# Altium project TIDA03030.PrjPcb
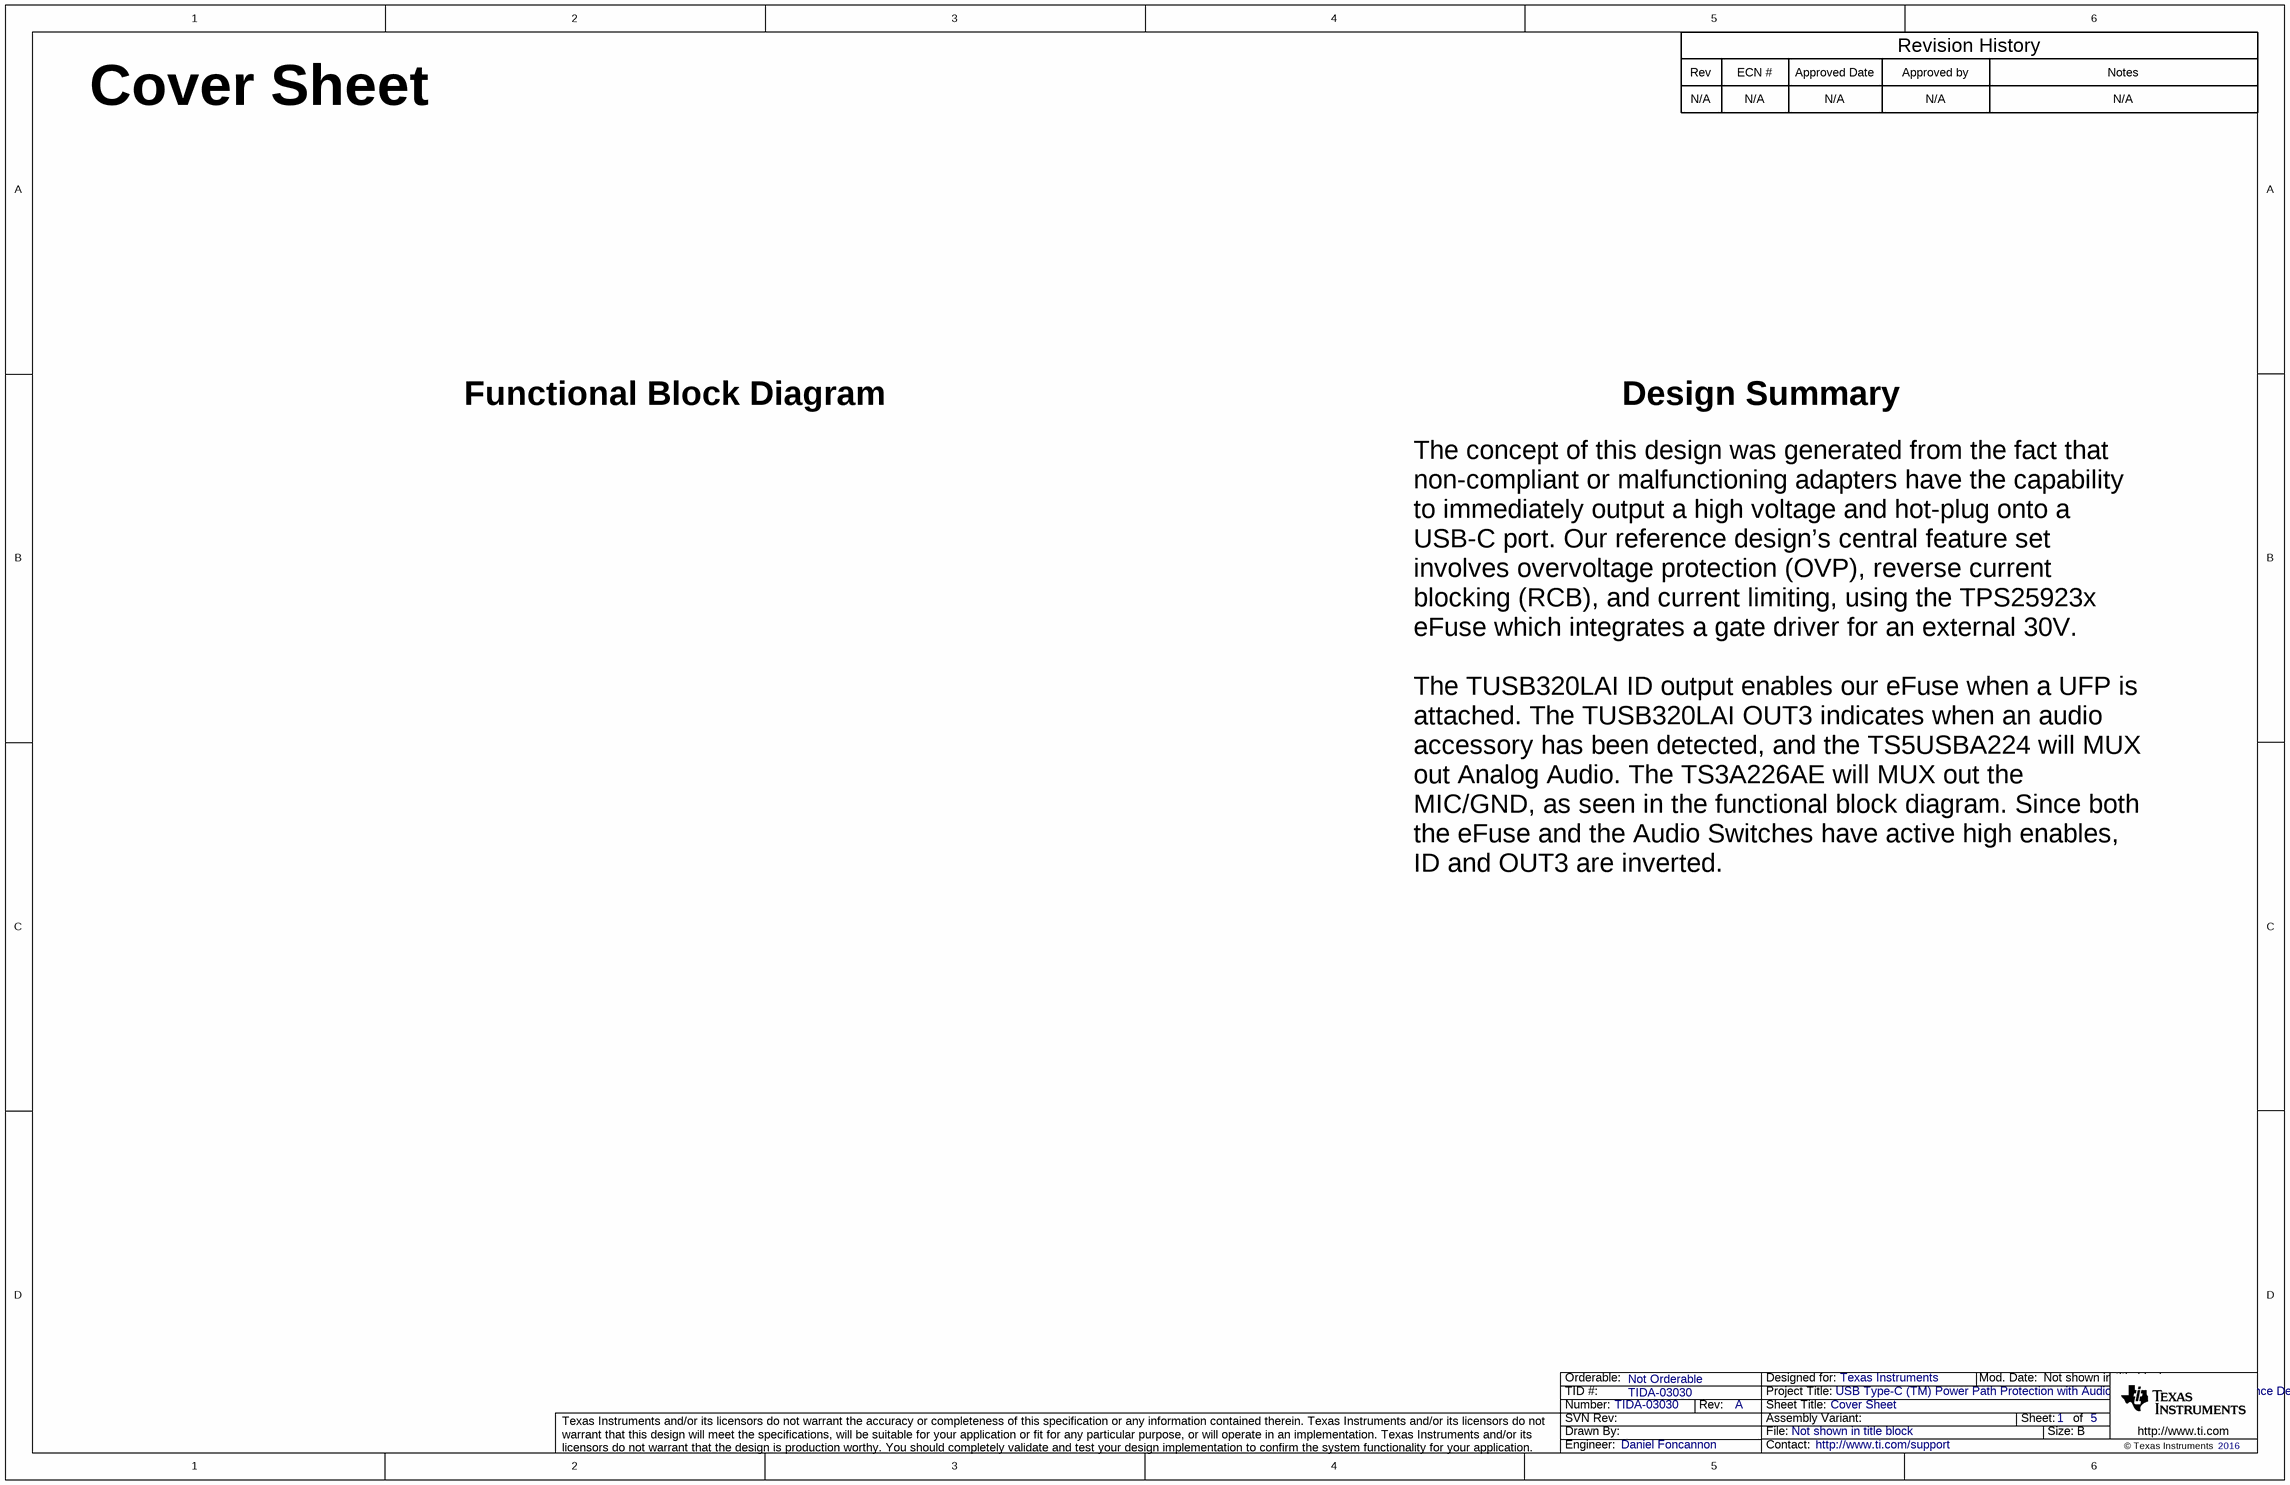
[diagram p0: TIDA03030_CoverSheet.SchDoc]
TID: TIDA-03030; TechSupport: http://www.ti.com/support; SCH_Rev: A; PRJ_Title: USB Type-C (TM) Power Path Protection with Audio Accessory Support Reference Design; PRJ_Number: TIDA-03030; PRJ_Engineer: Daniel Foncannon; PRJ_Customer: Texas Instruments; PCB_Rev: A; PCB_Layout: TIDA; EVM_Orderable: Not Orderable; CopyrightYear: 2016
5 sheets, 102 parts. Net scope: global (net labels, ports and power ports of the same name join across sheets).
Board file: TIDA03030_PCB.PcbDoc
Sheets:
  TIDA03030_CoverSheet.SchDoc
  TIDA03030_Hardware.SchDoc
  TIDA03030_Power.SchDoc
  TIDA03030_Controller&Switches.SchDoc
  TIDA03030_Connectors.SchDoc

## Sheet TIDA03030_CoverSheet.SchDoc: Cover Sheet
size 431 x 279 mm; Date: Not shown in title block; ApprovedBy: Not shown in title block; CheckedBy: Not shown in title block; Author: Not shown in title block; CompanyName: Not shown in title block; Engineer: Not shown in title block; Organization: Not shown in title block; Address1: Not shown in title block; Address2: Not shown in title block; Address3: Not shown in title block; Address4: Not shown in title block; DocumentNumber: 1; Revision: Use project parameter SCH_Rev; SheetNumber: 1; SheetTotal: 5; PageSetup: Record=PageOptions¦CenterHorizontal=True¦CenterVertical=True¦PrintScale=1.00¦XCorrection=1.00¦YCorrection=1.00¦PrintKind=0¦BorderSize=5000000¦LeftOffset=0¦BottomOffset=0¦Orientation=2¦PaperLength=1000¦PaperWidth=1000¦Scale=100¦PaperSource=15¦PrintQuality=600¦MediaType=1¦DitherType=10¦PaperKind=Letter¦PrintScaleMode=1

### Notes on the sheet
- Cover Sheet
- Rev
- N/A
- ECN #
- Approved Date
- Approved by
- Revision History
- Notes
- Functional Block Diagram
- Design Summary
- The concept of this design was generated from the fact that non-compliant or malfunctioning adapters have the capability to immediately output a high voltage and hot-plug onto a USB-C port. Our reference design’s central feature set involves overvoltage protection (OVP), reverse current blocking (RCB), and current limiting, using the TPS25923x eFuse which integrates a gate driver for an external 30V.
  The TUSB320LAI ID output enables our eFuse when a UFP is attached. The TUSB320LAI OUT3 indicates when an audio accessory has been detected, and the TS5USBA224 will MUX out Analog Audio. The TS3A226AE will MUX out the MIC/GND, as seen in the functional block diagram. Since both the eFuse and the Audio Switches have active high enables, ID and OUT3 are inverted.

## Sheet TIDA03030_Hardware.SchDoc: Board Hardware
size 431 x 279 mm; Date: Not shown in title block; ApprovedBy: Not shown in title block; CheckedBy: Not shown in title block; Author: Not shown in title block; CompanyName: Not shown in title block; Engineer: Not shown in title block; Organization: Not shown in title block; Address1: Not shown in title block; Address2: Not shown in title block; Address3: Not shown in title block; Address4: Not shown in title block; DocumentNumber: 5; Revision: Use project parameter SCH_Rev; SheetNumber: 5; SheetTotal: 5; PageSetup: Record=PageOptions¦CenterHorizontal=True¦CenterVertical=True¦PrintScale=1.00¦XCorrection=1.00¦YCorrection=1.00¦PrintKind=0¦BorderSize=5000000¦LeftOffset=0¦BottomOffset=0¦Orientation=2¦PaperLength=1000¦PaperWidth=1000¦Scale=100¦PaperSource=15¦PrintQuality=600¦MediaType=1¦DitherType=10¦PaperKind=Letter¦PrintScaleMode=1
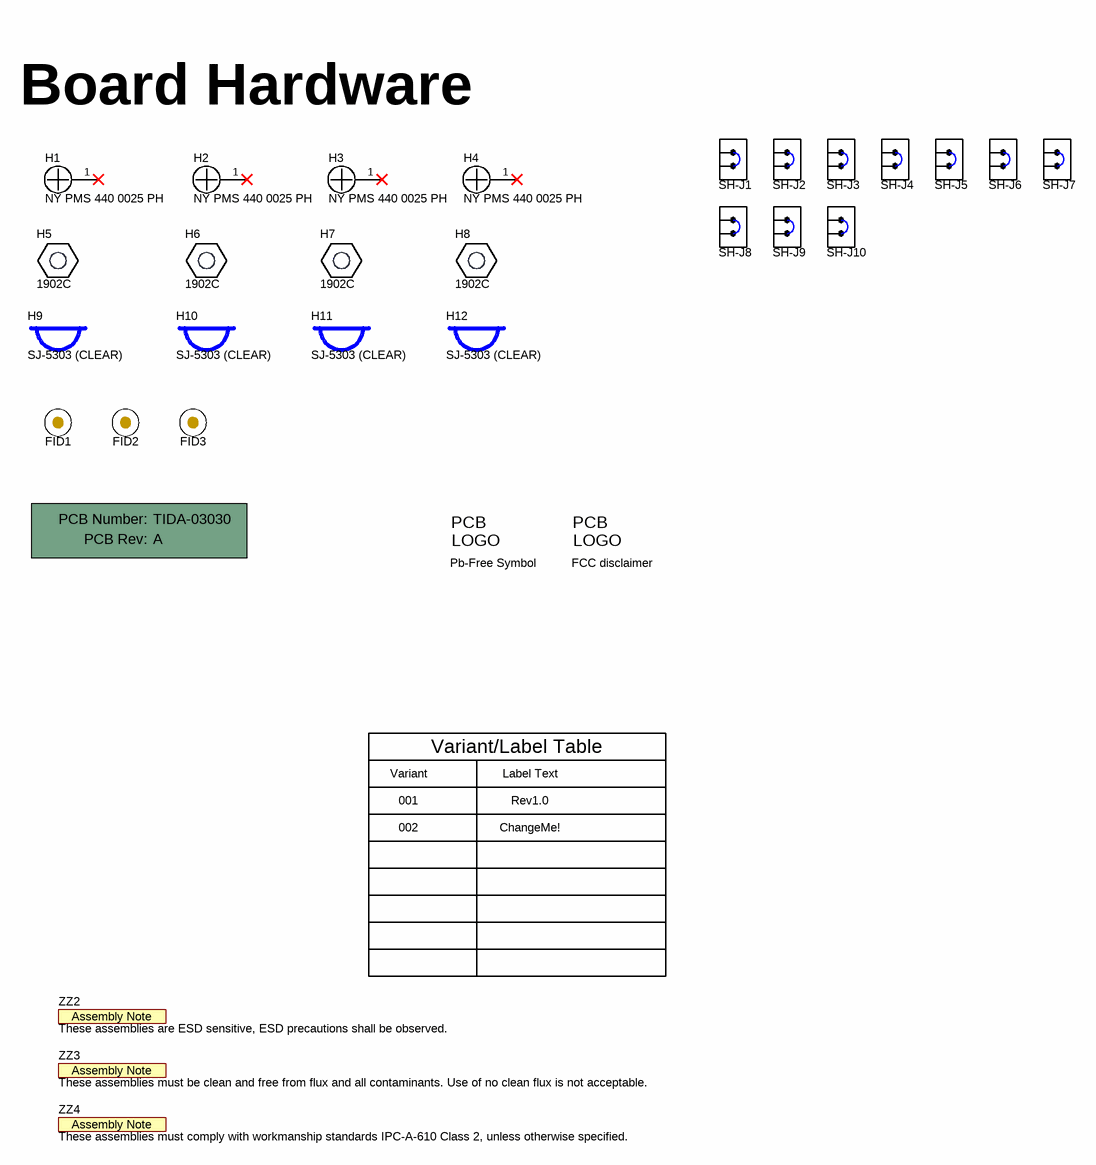
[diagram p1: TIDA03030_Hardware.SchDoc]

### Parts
!PCB1  Printed Circuit Board  (value not drawn)  (mechanical)
FID1  Fiducial  [Fiducial10-20]  (value not drawn)
FID2  Fiducial  [Fiducial10-20]  (value not drawn)
FID3  Fiducial  [Fiducial10-20]  (value not drawn)
H1  NY PMS 440 0025 PH  [NY PMS 440 0025 PH]
H2  NY PMS 440 0025 PH  [NY PMS 440 0025 PH]
H3  NY PMS 440 0025 PH  [NY PMS 440 0025 PH]
H4  NY PMS 440 0025 PH  [NY PMS 440 0025 PH]
H5  1902C  [Keystone_1902C]
H6  1902C  [Keystone_1902C]
H7  1902C  [Keystone_1902C]
H8  1902C  [Keystone_1902C]
H9  SJ-5303 (CLEAR)  [Bumpon_SJ5003Transparent]
H10  SJ-5303 (CLEAR)  [Bumpon_SJ5003Transparent]
H11  SJ-5303 (CLEAR)  [Bumpon_SJ5003Transparent]
H12  SJ-5303 (CLEAR)  [Bumpon_SJ5003Transparent]
Logo2  Pb-Free Symbol  [Pb-Free_Overlay_Small]  (no BOM)
Logo3  FCC disclaimer  [FCC_disclaimer]  (no BOM)
SH-J1  SNT-100-BK-G  [SNT-100-BK-G]  (value not drawn)
SH-J2  SNT-100-BK-G  [SNT-100-BK-G]  (value not drawn)
SH-J3  SNT-100-BK-G  [SNT-100-BK-G]  (value not drawn)
SH-J4  SNT-100-BK-G  [SNT-100-BK-G]  (value not drawn)
SH-J5  SNT-100-BK-G  [SNT-100-BK-G]  (value not drawn)
SH-J6  SNT-100-BK-G  [SNT-100-BK-G]  (value not drawn)
SH-J7  SNT-100-BK-G  [SNT-100-BK-G]  (value not drawn)
SH-J8  SNT-100-BK-G  [SNT-100-BK-G]  (value not drawn)
SH-J9  SNT-100-BK-G  [SNT-100-BK-G]  (value not drawn)
SH-J10  SNT-100-BK-G  [SNT-100-BK-G]  (value not drawn)
ZZ2  These assemblies are ESD sensitive, ESD precautions shall be observed.  [AssemblyNote]  (no BOM)
ZZ3  These assemblies must be clean and free from flux and all contaminants. Use of no clean flux is not acceptable.  [AssemblyNote]  (no BOM)
ZZ4  These assemblies must comply with workmanship standards IPC-A-610 Class 2, unless otherwise specified.  [AssemblyNote]  (no BOM)

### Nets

Not connected (* = marked no-connect by the designer): H1 1*; H2 1*; H3 1*; H4 1*

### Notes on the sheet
- Board Hardware
- Variant
- Variant/Label Table
- Label Text
- 001
- 002
- Rev1.0
- ChangeMe!

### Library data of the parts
!PCB1 = PCB: Manufacturer: Any; PartNumber: TIDA-03030; SymbolCreator: a0412235
FID1-FID3 = Fiducial: Fiducial mark.  There is nothing to buy or mount.; SymbolCreator: codlsc
H1-H4 = NY PMS 440 0025 PH: Machine Screw, Round, #4-40 x 1/4, Nylon, Philips panhead; Manufacturer: B&F Fastener Supply; CompType: Hardware; SymbolCreator: codlsc; U/M: EA
H5-H8 = 1902C: Standoff, Hex, 0.5"L #4-40 Nylon; Manufacturer: Keystone; CompType: Hardware
H9-H12 = SJ-5303 (CLEAR): Bumpon, Hemisphere, 0.44 X 0.20, Clear; Manufacturer: 3M; SymbolCreator: a0412235
Logo2 = Pb-Free: SymbolCreator: a0412235
Logo3 = FCC_disclaimer: SymbolCreator: codlsc
SH-J1-SH-J10 = SNT-100-BK-G: Shunt, 100mil, Gold plated, Black; Manufacturer: Samtec; Alternate Manufacturer: 3M; Alternate PartNumber: 969102-0000-DA; Value: 1x2; Note: You can "mate" this to a header by matching the designator.  i.e. use SH-J3 for header J3
ZZ2-ZZ4 = AssemblyNote: SymbolCreator: codlsc

## Sheet TIDA03030_Power.SchDoc: Power
size 431 x 279 mm; Date: Not shown in title block; ApprovedBy: Not shown in title block; CheckedBy: Not shown in title block; Author: Not shown in title block; CompanyName: Not shown in title block; Engineer: Not shown in title block; Organization: Not shown in title block; Address1: Not shown in title block; Address2: Not shown in title block; Address3: Not shown in title block; Address4: Not shown in title block; DocumentNumber: 3; Revision: Use project parameter SCH_Rev; SheetNumber: 3; SheetTotal: 5; PageSetup: Record=PageOptions¦CenterHorizontal=True¦CenterVertical=True¦PrintScale=1.00¦XCorrection=1.00¦YCorrection=1.00¦PrintKind=0¦BorderSize=5000000¦LeftOffset=0¦BottomOffset=0¦Orientation=2¦PaperLength=1000¦PaperWidth=1000¦Scale=100¦PaperSource=15¦PrintQuality=600¦MediaType=1¦DitherType=10¦PaperKind=Letter¦PrintScaleMode=1
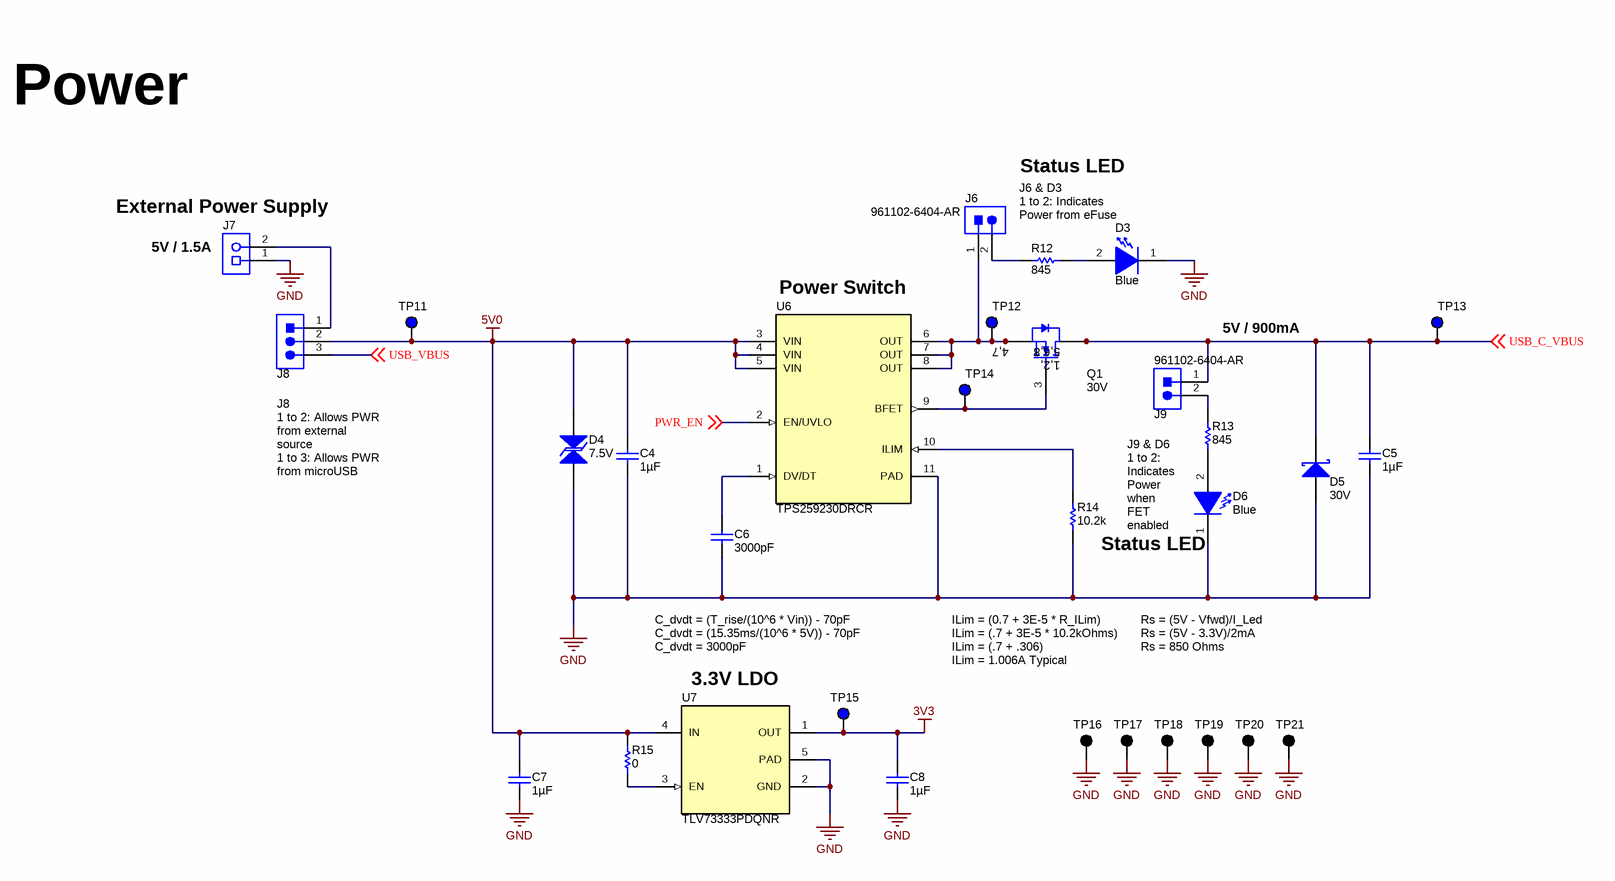
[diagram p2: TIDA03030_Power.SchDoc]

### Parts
C4  ValueDisplayed: 1µF  [0603]  (hidden comment: GCM188R71C105KA64D)
C5  ValueDisplayed: 1µF  [0603]  (hidden comment: GCM188R71C105KA64D)
C6  ValueDisplayed: 3000pF  [0603]  (hidden comment: GRM1885C1H302JA01D)
C7  ValueDisplayed: 1µF  [1206_180]  (hidden comment: C3216X7R1H105K160AB)
C8  ValueDisplayed: 1µF  [1206_180]  (hidden comment: C3216X7R1H105K160AB)
D3  value Blue  [WL-SMCW_Blue]  (hidden comment: 150060BS75000)
D4  value 7.5V  [SMA]  (hidden comment: SMAJ7.5CA)
D5  30V  [SOD-123]
D6  value Blue  [WL-SMCW_Blue]  (hidden comment: 150060BS75000)
J6  961102-6404-AR  [3M_961102-6404-AR]
J7  282841-2  [TEC_282841-2]  (value not drawn)
J8  HTSW-103-09-G-S  [Samtec_HTSW-103-09-x-S]  (value not drawn)
J9  961102-6404-AR  [3M_961102-6404-AR]
Q1  30V  [TRANS_NexFET_Q2]
R12  ValueDisplayed: 845  [0603]  (hidden comment: CRCW0603845RFKEA)
R13  ValueDisplayed: 845  [0603]  (hidden comment: CRCW0603845RFKEA)
R14  ValueDisplayed: 10.2k  [0805_HV]  (hidden comment: CRCW080510K2FKEA)
R15  ValueDisplayed: 0  [0603]  (hidden comment: CRCW06030000Z0EA)
TP11  5117  [Keystone5117]  (value not drawn)
TP12  5117  [Keystone5117]  (value not drawn)
TP13  5117  [Keystone5117]  (value not drawn)
TP14  5117  [Keystone5117]  (value not drawn)
TP15  5117  [Keystone5117]  (value not drawn)
TP16  5001  [Keystone5001]  (value not drawn)
TP17  5001  [Keystone5001]  (value not drawn)
TP18  5001  [Keystone5001]  (value not drawn)
TP19  5001  [Keystone5001]  (value not drawn)
TP20  5001  [Keystone5001]  (value not drawn)
TP21  5001  [Keystone5001]  (value not drawn)
U6  TPS259230DRCR  [DRC0010J]
U7  TLV73333PDQNR  [DQN0004A]

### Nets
3V3: C8.1 TP15.1 U7.1(OUT)
5V0: C4.1 C7.1 D4.2 J8.2 R15.2 TP11.1 U6.3(VIN) U6.4(VIN) U6.5(VIN) U7.4(IN)
GND: C4.2 C5.2 C6.2 C7.2 C8.2 D3.1(K) D4.1 D5.2(A) D6.1(K) J7.1 R14.1 TP16.1 TP17.1 TP18.1 TP19.1 TP20.1 TP21.1 U6.11(PAD) U7.2(GND) U7.5(PAD)
PWR_EN: U6.2(EN/UVLO) ; off-sheet PWR_EN
USB_C_VBUS: C5.1 D5.1(K) J9.1 Q1.1(D) Q1.2(D) Q1.5(D) Q1.6(D) Q1.8(D) TP13.1 ; off-sheet USB_C_VBUS
USB_VBUS: J8.3 ; off-sheet USB_VBUS
NetC6_1: C6.1 U6.1(DV/DT)
NetD3_2: D3.2(A) R12.1
NetD6_2: D6.2(A) R13.1
NetJ6_1: J6.1 Q1.4(S) Q1.7(S) TP12.1 U6.6(OUT) U6.7(OUT) U6.8(OUT)
NetJ6_2: J6.2 R12.2
NetJ7_2: J7.2 J8.1
NetJ9_2: J9.2 R13.2
NetQ1_3: Q1.3(G) TP14.1 U6.9(BFET)
NetR14_2: R14.2 U6.10(ILIM)
NetR15_1: R15.1 U7.3(EN)

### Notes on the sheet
- Power
- (near J7) External Power Supply
- Status LED
- (near J7) 5V / 1.5A
- J6 & D3
  1 to 2: Indicates Power from eFuse
- (near U6) Power Switch
- 5V / 900mA
- (near J8) J8
  1 to 2: Allows PWR from external source
  1 to 3: Allows PWR from microUSB connector
- J9 & D6
  1 to 2: Indicates Power when FET enabled
- C_dvdt = (T_rise/(10^6 * Vin)) - 70pF
  C_dvdt = (15.35ms/(10^6 * 5V)) - 70pF
  C_dvdt = 3000pF
- (near U7) 3.3V LDO
- ILim = (0.7 + 3E-5 * R_ILim)
  ILim = (.7 + 3E-5 * 10.2kOhms)
  ILim = (.7 + .306)
  ILim = 1.006A Typical
- Rs = (5V - Vfwd)/I_Led
  Rs = (5V - 3.3V)/2mA
  Rs = 850 Ohms

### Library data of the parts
C4 C5 = GCM188R71C105KA64D: CAP, CERM, 1 µF, 16 V, +/- 10%, X7R, AEC-Q200 Grade 1, 0603; Manufacturer: MuRata; Polarized: N; CompType: Capacitor; Value: 1uF; U/M: EA; Cap_F: 0.000001; Tolerance_%: 10; Value1: Unknown; VDC_V: 16; Value2: 16V; TaMin_C: -55; TaMax_C: 125; SizeArea_mm2: 1.28; SizeAreaWB_mm2: 4.68; SizeX_mm: 1.6; SizeY_mm: 0.8; SizeZ_mm: 1; AEC Category: Q200; AEC Qualified: Y
C6 = GRM1885C1H302JA01D: CAP, CERM, 3000 pF, 50 V, +/- 5%, C0G/NP0, 0603; Manufacturer: MuRata; Polarized: N; CompType: Capacitor; Value: 3000pF; U/M: EA; Cap_F: 0.000000003; Tolerance_%: 5; Value1: Unknown; VDC_V: 50; Value2: 50V; TaMin_C: -55; TaMax_C: 125; SizeArea_mm2: 1.28; SizeAreaWB_mm2: 4.68; SizeX_mm: 1.6; SizeY_mm: 0.8; SizeZ_mm: 1; AEC Category: Q200
C7 C8 = C3216X7R1H105K160AB: CAP, CERM, 1 µF, 50 V, +/- 10%, X7R, 1206; Manufacturer: TDK; Polarized: N; CompType: Capacitor; Value: 1uF; U/M: EA; Cap_F: 0.000001; Tolerance_%: 10; ESR_ohm: 0.009289; Value1: 0.009289 ohm; VDC_V: 50; Value2: 50V; IRMS_A: 2.38446; TaMin_C: -55; TaMax_C: 125; SizeArea_mm2: 5.12; SizeAreaWB_mm2: 10.92; SizeX_mm: 3.2; SizeY_mm: 1.6; SizeZ_mm: 1.8; AEC Category: Q200
D3 D6 = 150060BS75000: LED, Blue, SMD; Manufacturer: Wurth Elektronik; Type: InGaN; Vf_V: 3.2; Value2: 3.2V; Io_A: 0.03; Vr_V: 5; Tjmax_C: 85; Power_TotalModule: 0.105; Value1: 0.105W; Angle: 140; U/M: EA
D4 = SMAJ7.5CA: Diode, TVS, Bi, 7.5 V, 400 W, SMA; Manufacturer: Littelfuse; U/M: EA; Power_W: 400; Vr_V: 7.5; Value1: 400W; RJA_CperW: 120; SizeAreaWB_mm2: 37.3428; SizeArea_mm2: 16.3228; SizeX_mm: 5.59; SizeY_mm: 2.92; SizeZ_mm: 2.87; AEC Category: Q101
D5 = MBR130T1G: Diode, Schottky, 30 V, 1 A, SOD-123; Manufacturer: ON Semiconductor; U/M: EA; Vf_V: 0.47; Value1: 1A; Value2: 0.47V; Io_A: 1; Vr_V: 30; TJmax_C: 125; RJC_CperW: 108; SizeAreaWB_mm2: 13.095; SizeArea_mm2: 6.545; SizeX_mm: 3.85; SizeY_mm: 1.7; SizeZ_mm: 1.35; AEC Category: Q101
J6 J9 = 961102-6404-AR: Header, 2.54mm, 2x1, TH; Manufacturer: 3M; SymbolCreator: a0412235; Pitch_mm: 2.54; Gender: Male; Shrouded: N; Row_Count: 1; ContactFinish: Gold; Current_A: 2; Voltage_V: 1000; Cert_UL: Y
J7 = 282841-2: Terminal Block, 2x1, 5.08mm, TH; Manufacturer: TE Connectivity; SymbolCreator: a0412235
J8 = HTSW-103-09-G-S: Header, 100mil, 3x1, Gold, TH; Manufacturer: Samtec; SymbolCreator: a0799628; Pitch_mm: 2.54; Gender: Male; Row_Count: 1; Cert_CSA: Y
Q1 = CSD17571Q2: MOSFET, N-CH, 30 V, 7.6 A, SON 2x2mm; Manufacturer: Texas Instruments; Alternate Manufacturer: None; U/M: EA; ChType: N; VdsMax_V: 30; Value1: 0.029 ohm; Rdson45_ohm: 0.029; Value2: 2.4 nC; QgTyp_nC: 2.4; Vgs_V: 20; IdsMax_A: 7.6; SizeAreaWB_mm2: 9; SizeArea_mm2: 4; SizeX_mm: 2; SizeZ_mm: 0.85; AEC Category: Q101
R12 R13 = CRCW0603845RFKEA: RES, 845, 1%, 0.1 W, 0603; Manufacturer: Vishay-Dale; CompType: Resistor; Value: 845; Value_Code: 845R; Tolerance_%: 1; Power_W: 0.1; Value2: 0.1W; VDC_V: 75; TempCo: 100 ppm/C; SizeArea_mm2: 1.28; SizeX_mm: 1.6; SizeY_mm: 0.8; EIA_Code: E96; U/M: EA; AEC Category: Q200
R14 = CRCW080510K2FKEA: RES, 10.2 k, 1%, 0.125 W, 0805; Manufacturer: Vishay-Dale; CompType: Resistor; Value: 10.2k; Res_ohm: 10200; Value_Code: 10k2; Tolerance_%: 1; Power_W: 0.125; Value2: 0.125W; VDC_V: 150; TempCo: 100 ppm/C; SizeArea_mm2: 2.5; SizeX_mm: 2; SizeY_mm: 1.25; SizeZ_mm: 1.45; EIA_Code: E96; U/M: EA; AEC Category: Q200
R15 = CRCW06030000Z0EA: RES, 0, 5%, 0.1 W, 0603; Manufacturer: Vishay-Dale; CompType: Resistor; Value: 0; Value_Code: 0000; Tolerance_%: 5; Power_W: 0.1; Value2: 0.1W; VDC_V: 75; TempCo: 200 ppm/C; SizeArea_mm2: 1.28; SizeX_mm: 1.6; SizeY_mm: 0.8; SizeZ_mm: 1; EIA_Code: E24; U/M: EA; AEC Category: Q200
TP11-TP15 = 5117: Test Point, Miniature, Blue, TH; Manufacturer: Keystone; CompType: Test Point Loop; U/M: EA; ContactFinish: Silver
TP16-TP21 = 5001: Test Point, Miniature, Black, TH; Manufacturer: Keystone; CompType: Test Point Loop; ContactFinish: Silver
U6 = TPS259230DRCR: 12-V eFuse with Over Voltage Protection and Blocking FET Control, DRC0010J; Alternate PartNumber: TPS259230DRCT; Manufacturer: Texas Instruments; SymbolCreator: a0799628; SizeArea_mm2: 9; SizeAreaWB_mm2: 16; SizeX_mm: 3; SizeZ_mm: 1; CompType: IC; U/M: EA
U7 = TLV73333PDQNR: Capacitor-Free, 300-mA, Low-Dropout Regulator, DQN0004A; Alternate PartNumber: TLV73333PDQNT; Manufacturer: Texas Instruments; SymbolCreator: Altium; SizeArea_mm2: 1; SizeAreaWB_mm2: 4; SizeZ_mm: 0.4; CompType: IC; U/M: EA

## Sheet TIDA03030_Controller&Switches.SchDoc: USB Type-C Controller and Switches
size 431 x 279 mm; Date: Not shown in title block; ApprovedBy: Not shown in title block; CheckedBy: Not shown in title block; Author: Not shown in title block; CompanyName: Not shown in title block; Engineer: Not shown in title block; Organization: Not shown in title block; Address1: Not shown in title block; Address2: Not shown in title block; Address3: Not shown in title block; Address4: Not shown in title block; DocumentNumber: 2; Revision: Use project parameter SCH_Rev; SheetNumber: 2; SheetTotal: 5; PageSetup: Record=PageOptions¦CenterHorizontal=True¦CenterVertical=True¦PrintScale=0.64¦XCorrection=1.00¦YCorrection=1.00¦PrintKind=0¦BorderSize=5000000¦LeftOffset=0¦BottomOffset=0¦Orientation=2¦PaperLength=1000¦PaperWidth=1000¦Scale=100¦PaperSource=15¦PrintQuality=600¦MediaType=1¦DitherType=10¦PrintScaleMode=1¦PaperKind=Letter
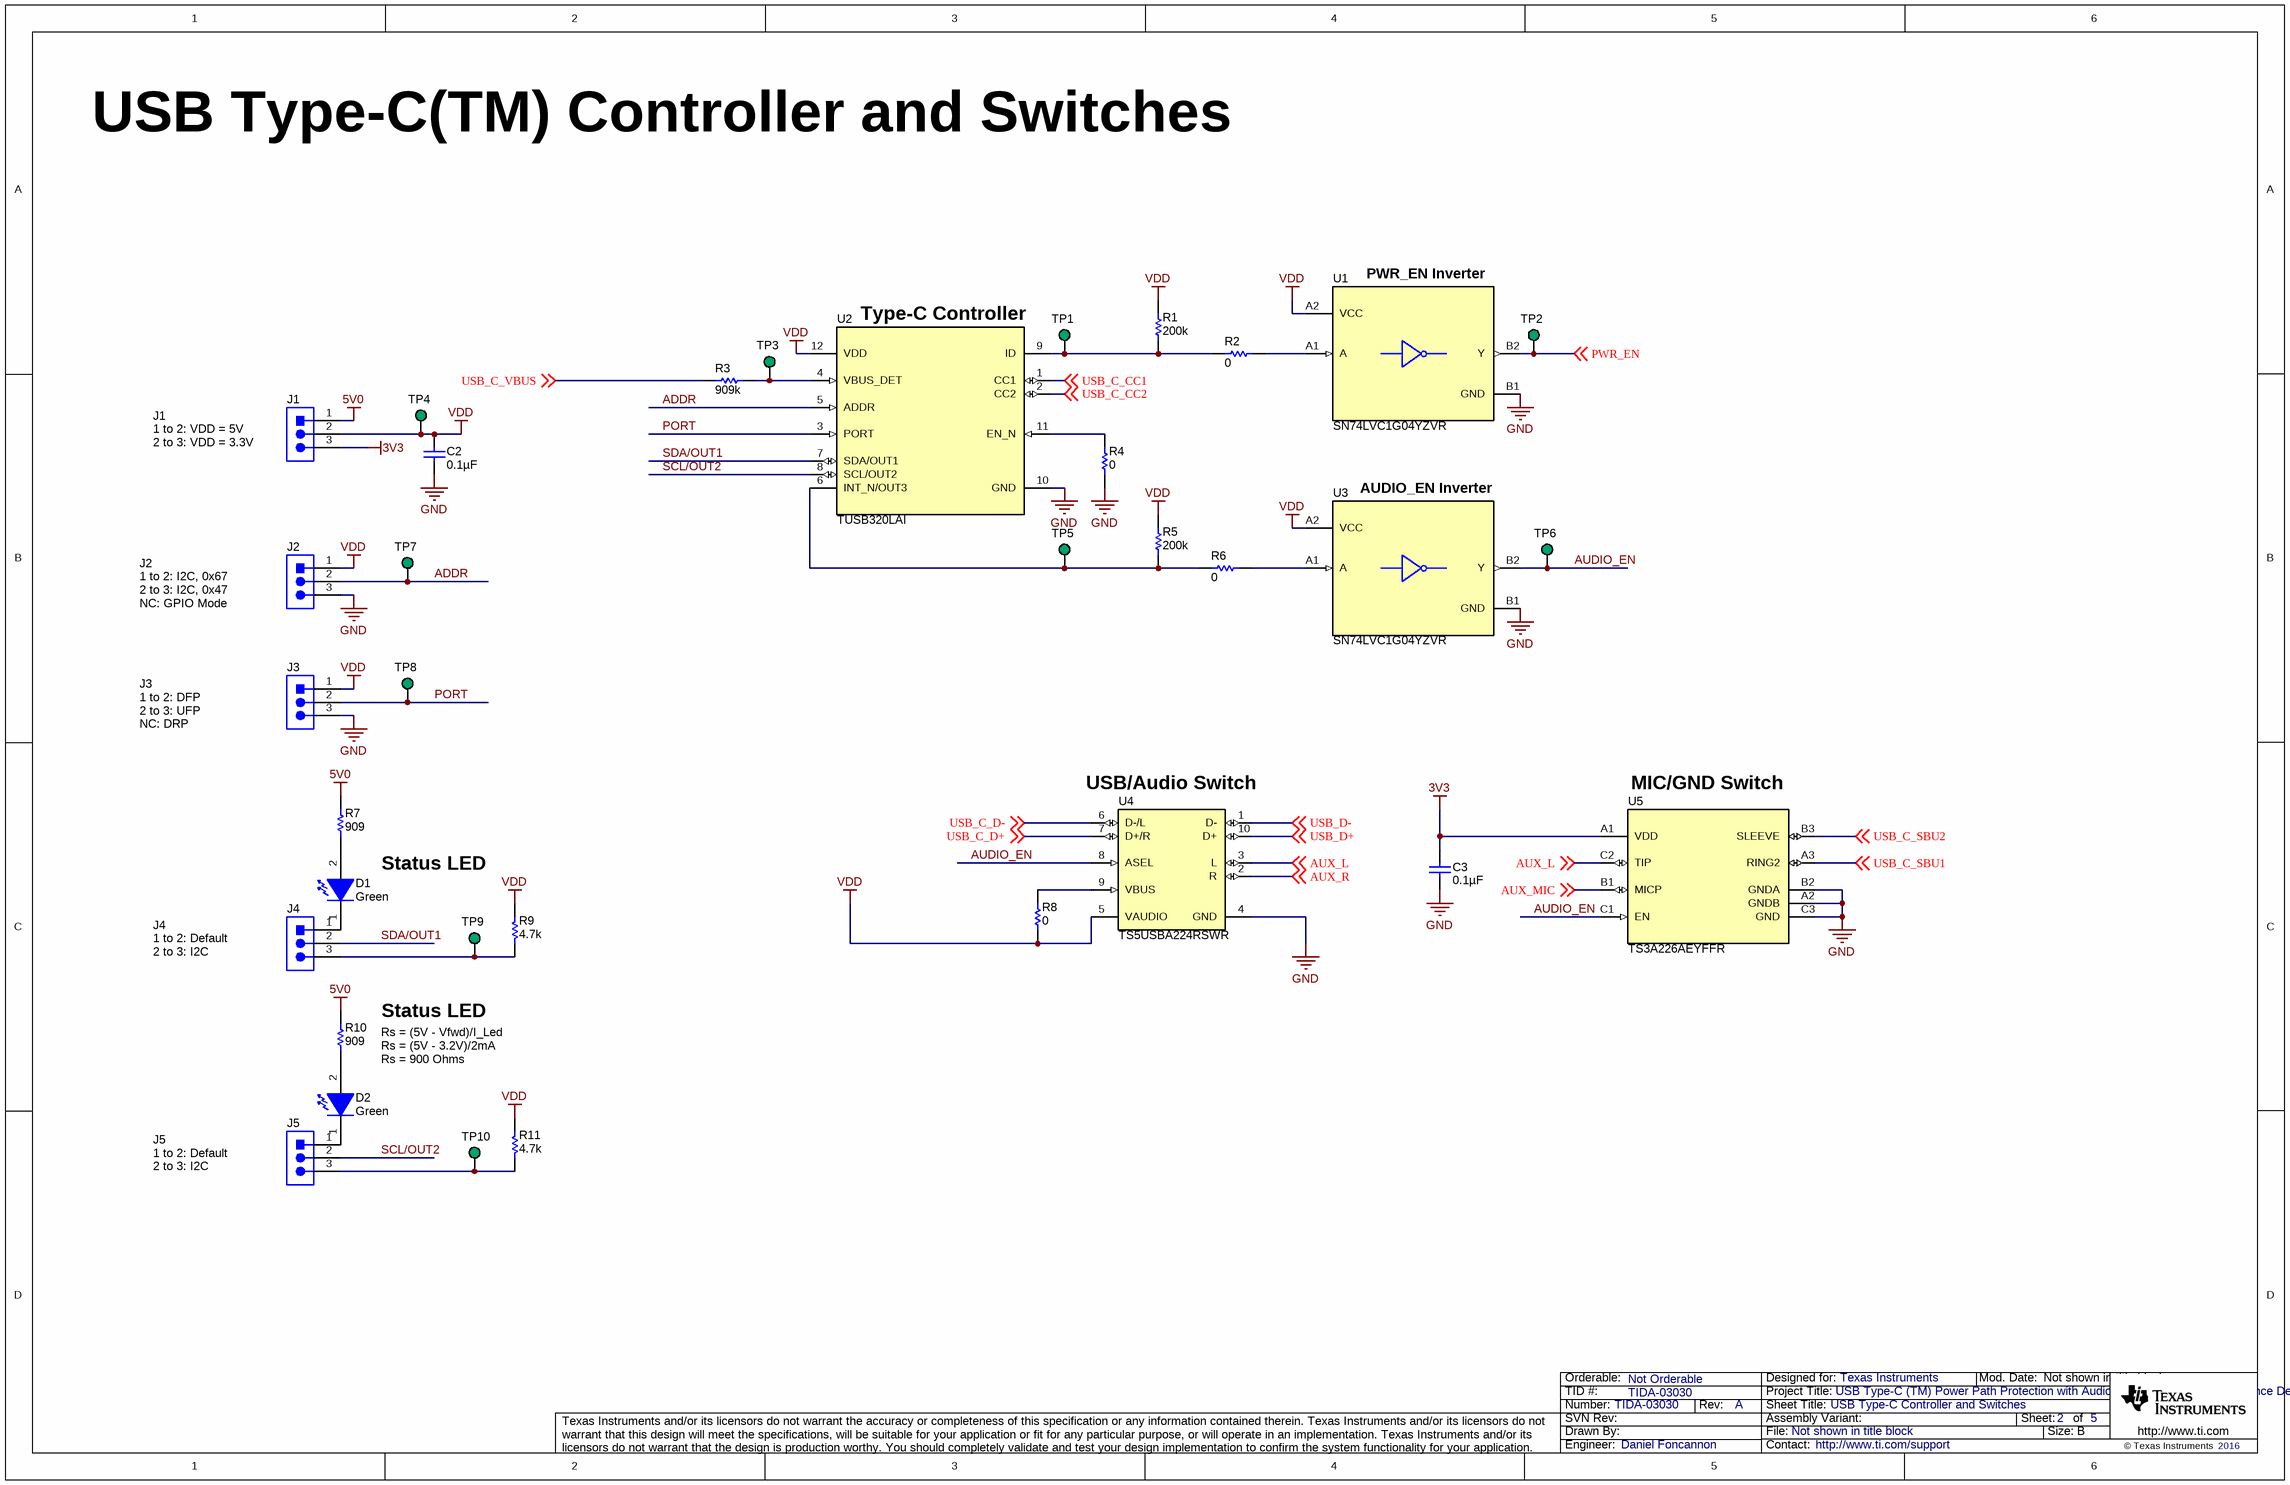
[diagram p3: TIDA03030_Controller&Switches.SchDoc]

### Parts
C2  ValueDisplayed: 0.1µF  [0402]  (hidden comment: GCM155R71C104KA55D)
C3  ValueDisplayed: 0.1µF  [0402]  (hidden comment: GCM155R71C104KA55D)
D1  value Green  [WL-SMCW_GREEN]  (hidden comment: 150060GS75000)
D2  value Green  [WL-SMCW_GREEN]  (hidden comment: 150060GS75000)
J1  HTSW-103-09-G-S  [Samtec_HTSW-103-09-x-S]  (value not drawn)
J2  HTSW-103-09-G-S  [Samtec_HTSW-103-09-x-S]  (value not drawn)
J3  HTSW-103-09-G-S  [Samtec_HTSW-103-09-x-S]  (value not drawn)
J4  HTSW-103-09-G-S  [Samtec_HTSW-103-09-x-S]  (value not drawn)
J5  HTSW-103-09-G-S  [Samtec_HTSW-103-09-x-S]  (value not drawn)
R1  ValueDisplayed: 200k  [0402]  (hidden comment: CRCW0402200KFKED)
R2  ValueDisplayed: 0  [0603]  (hidden comment: CRCW06030000Z0EA)
R3  ValueDisplayed: 909k  [0402]  (hidden comment: CRCW0402909KFKED)
R4  ValueDisplayed: 0  [0603]  (hidden comment: CRCW06030000Z0EA)
R5  ValueDisplayed: 200k  [0402]  (hidden comment: CRCW0402200KFKED)
R6  ValueDisplayed: 0  [0603]  (hidden comment: CRCW06030000Z0EA)
R7  ValueDisplayed: 909  [0603]  (hidden comment: RC0603FR-07909RL)
R8  ValueDisplayed: 0  [0603]  (hidden comment: CRCW06030000Z0EA)
R9  ValueDisplayed: 4.7k  [0402]  (hidden comment: CRCW04024K70JNED)
R10  ValueDisplayed: 909  [0603]  (hidden comment: RC0603FR-07909RL)
R11  ValueDisplayed: 4.7k  [0402]  (hidden comment: CRCW04024K70JNED)
TP1  5116  [Keystone_5116]  (value not drawn)
TP2  5116  [Keystone_5116]  (value not drawn)
TP3  5116  [Keystone_5116]  (value not drawn)
TP4  5116  [Keystone_5116]  (value not drawn)
TP5  5116  [Keystone_5116]  (value not drawn)
TP6  5116  [Keystone_5116]  (value not drawn)
TP7  5116  [Keystone_5116]  (value not drawn)
TP8  5116  [Keystone_5116]  (value not drawn)
TP9  5116  [Keystone_5116]  (value not drawn)
TP10  5116  [Keystone_5116]  (value not drawn)
U1  SN74LVC1G04YZVR  [YZV0004ADAD]
U2  TUSB320LAI  [RWB0012A]
U3  SN74LVC1G04YZVR  [YZV0004ADAD]
U4  TS5USBA224RSWR  [RSW0010A]
U5  TS3A226AEYFFR  [YFF0009AEAJ]

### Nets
3V3: C3.1 J1.3 U5.A1(VDD)
5V0: J1.1 R7.2 R10.2
GND: C2.2 C3.2 J2.3 J3.3 R4.1 U1.B1(GND) U2.10(GND) U3.B1(GND) U4.4(GND) U5.A2(GNDB) U5.B2(GNDA) U5.C3(GND)
VDD: C2.1 J1.2 J2.1 J3.1 R1.1 R5.1 R8.1 R9.2 R11.2 TP4.1 U1.A2(VCC) U2.12(VDD) U3.A2(VCC) U4.5(VAUDIO)
ADDR: J2.2 TP7.1 U2.5(ADDR)
AUDIO_EN: TP6.1 U3.B2(Y) U4.8(ASEL) U5.C1(EN)
AUX_L: U4.3(L) U5.C2(TIP) ; off-sheet AUX_L
AUX_MIC: U5.B1(MICP) ; off-sheet AUX_MIC
AUX_R: U4.2(R) ; off-sheet AUX_R
PORT: J3.2 TP8.1 U2.3(PORT)
PWR_EN: TP2.1 U1.B2(Y) ; off-sheet PWR_EN
SCL/OUT2: J5.2 U2.8(SCL/OUT2)
SDA/OUT1: J4.2 U2.7(SDA/OUT1)
USB_C_CC1: U2.1(CC1) ; off-sheet USB_C_CC1
USB_C_CC2: U2.2(CC2) ; off-sheet USB_C_CC2
USB_C_D+: U4.7(D+/R) ; off-sheet USB_C_D+
USB_C_D-: U4.6(D-/L) ; off-sheet USB_C_D-
USB_C_SBU1: U5.A3(RING2) ; off-sheet USB_C_SBU1
USB_C_SBU2: U5.B3(SLEEVE) ; off-sheet USB_C_SBU2
USB_C_VBUS: R3.2 ; off-sheet USB_C_VBUS
USB_D+: U4.10(D+) ; off-sheet USB_D+
USB_D-: U4.1(D-) ; off-sheet USB_D-
NetD1_1: D1.1(K) J4.1
NetD1_2: D1.2(A) R7.1
NetD2_1: D2.1(K) J5.1
NetD2_2: D2.2(A) R10.1
NetJ4_3: J4.3 R9.1 TP9.1
NetJ5_3: J5.3 R11.1 TP10.1
NetR1_2: R1.2 R2.2 TP1.1 U2.9(ID)
NetR2_1: R2.1 U1.A1(A)
NetR3_1: R3.1 TP3.1 U2.4(VBUS_DET)
NetR4_2: R4.2 U2.11(EN_N)
NetR5_2: R5.2 R6.2 TP5.1 U2.6(INT_N/OUT3)
NetR6_1: R6.1 U3.A1(A)
NetR8_2: R8.2 U4.9(VBUS)

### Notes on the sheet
- USB Type-C(TM) Controller and Switches
- (near U1) PWR_EN Inverter
- Type-C Controller
- (near J1) J1
  1 to 2: VDD = 5V
  2 to 3: VDD = 3.3V
- (near U3) AUDIO_EN Inverter
- J2
  1 to 2: I2C, 0x67
  2 to 3: I2C, 0x47
  NC: GPIO Mode
- J3
  1 to 2: DFP
  2 to 3: UFP
  NC: DRP
- (near U4) USB/Audio Switch
- (near U5) MIC/GND Switch
- Status LED
- (near J4) J4
  1 to 2: Default
  2 to 3: I2C
- Rs = (5V - Vfwd)/I_Led
  Rs = (5V - 3.2V)/2mA
  Rs = 900 Ohms
- (near J5) J5
  1 to 2: Default
  2 to 3: I2C

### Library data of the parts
C2 C3 = GCM155R71C104KA55D: CAP, CERM, 0.1 µF, 16 V, +/- 10%, X7R, 0402; Manufacturer: MuRata; Polarized: N; CompType: Capacitor; Value: 0.1uF; U/M: EA; Cap_F: 0.0000001; Tolerance_%: 10; Value1: Unknown; VDC_V: 16; Value2: 16V; TaMin_C: -55; TaMax_C: 125; SizeArea_mm2: 0.5; SizeAreaWB_mm2: 3; SizeX_mm: 1; SizeZ_mm: 0.6; AEC Category: Q200
D1 D2 = 150060GS75000: LED, Green, SMD; Manufacturer: Wurth Elektronik; Type: InGaN; Vf_V: 3.2; Value2: 3.2V; Io_A: 0.02; Tjmax_C: 85; Value1: W; Angle: 140; U/M: EA
J1-J5 = HTSW-103-09-G-S: as J8 on sheet TIDA03030_Power
R1 R5 = CRCW0402200KFKED: RES, 200 k, 1%, 0.063 W, 0402; Manufacturer: Vishay-Dale; CompType: Resistor; Value: 200k; Res_ohm: 200000; Tolerance_%: 1; Power_W: 0.063; Value2: 0.063W; VDC_V: 50; TempCo: 100 ppm/C; SizeArea_mm2: 0.5; SizeZ_mm: 0.6; EIA_Code: E96; U/M: EA; AEC Category: Q200
R2 R4 R6 R8 = CRCW06030000Z0EA: as R15 on sheet TIDA03030_Power
R3 = CRCW0402909KFKED: RES, 909 k, 1%, 0.063 W, 0402; Manufacturer: Vishay-Dale; CompType: Resistor; Value: 909k; Res_ohm: 909000; Tolerance_%: 1; Power_W: 0.063; Value2: 0.063W; VDC_V: 50; TempCo: 100 ppm/C; SizeArea_mm2: 0.5; SizeZ_mm: 0.6; EIA_Code: E96; U/M: EA; AEC Category: Q200
R7 R10 = RC0603FR-07909RL: RES, 909, 1%, 0.1 W, 0603; Manufacturer: Yageo America; CompType: Resistor; Value: 909; Value_Code: 909R; Tolerance_%: 1; Power_W: 0.1; Value2: 0.1W; VDC_V: 150; TempCo: 200 ppm/C; EIA_Code: E96; U/M: EA; AEC Category: Q200
R9 R11 = CRCW04024K70JNED: RES, 4.7 k, 5%, 0.063 W, 0402; Manufacturer: Vishay-Dale; CompType: Resistor; Value: 4.7k; Res_ohm: 4700; Value_Code: 4k70; Tolerance_%: 5; Power_W: 0.063; Value2: 0.063W; VDC_V: 50; TempCo: 200 ppm/C; SizeArea_mm2: 0.5; SizeX_mm: 1; SizeZ_mm: 0.6; EIA_Code: E24; U/M: EA; AEC Category: Q200
TP1-TP10 = 5116: Test Point, Miniature, Green, TH; Manufacturer: Keystone; SymbolCreator: a0412235; CompType: Test Point Loop; Row_Count: 1; ContactFinish: Silver; Cert_UL: Y
U1 U3 = SN74LVC1G04YZVR: Single Inverter Gate, YZV0004ADAD; Manufacturer: Texas Instruments; SymbolCreator: Altium; SizeArea_mm2: 1.5625; SizeAreaWB_mm2: 5.0625; SizeX_mm: 1.25; SizeZ_mm: 0.5; CompType: IC; U/M: EA
U2 = TUSB320IRWBR: USB Type-C Configuration Channel Logic and Port Control, RWB0012A; Manufacturer: Texas Instruments; SymbolCreator: Altium; SizeArea_mm2: 2.56; SizeAreaWB_mm2: 6.76; SizeX_mm: 1.6; SizeZ_mm: 0.4; CompType: IC; U/M: EA
U4 = TS5USBA224RSWR: USB 2.0 High-Speed (480Mbps) and Audio Switches with Negative Signal Capability,3 / 4 ohm RON, -40 to 85 degC, 10-Pin UQFN (RSW), Green (RoHS & no Sb/Br); Manufacturer: Texas Instruments; Alternate PartNumber: Equivalent; SubFamily: USB Switch; Number of Channels: 2; Architecture: 1; ICC(uA): 6; OFF Time(Max)(ns): 1000; Vcc range(V): 2.7 to 5.5; IL OFF(Max)(nA): +/-50; RON Flatness(Max)(Ohms): 1.5; RON Mis-match(Max)(Ohms): 0.3; Bandwidth(MHz): 650; ON Time(Max)(ns): 4000
U5 = TS3A226AEYFFR: Autonomous Audio Headset Switch with Reduced GND Switch RON and FM Capability,YFF0009AEAJ; Manufacturer: Texas Instruments; SymbolCreator: Altium; SizeArea_mm2: 1.703136; SizeAreaWB_mm2: 5.315136; SizeX_mm: 1.256; SizeY_mm: 1.356; SizeZ_mm: 0.625; CompType: IC; U/M: EA

## Sheet TIDA03030_Connectors.SchDoc: Connectors and ESD Protection
size 431 x 279 mm; Date: Not shown in title block; ApprovedBy: Not shown in title block; CheckedBy: Not shown in title block; Author: Not shown in title block; CompanyName: Not shown in title block; Engineer: Not shown in title block; Organization: Not shown in title block; Address1: Not shown in title block; Address2: Not shown in title block; Address3: Not shown in title block; Address4: Not shown in title block; DocumentNumber: 4; Revision: Use project parameter SCH_Rev; SheetNumber: 4; SheetTotal: 5; PageSetup: Record=PageOptions¦CenterHorizontal=True¦CenterVertical=True¦PrintScale=1.00¦XCorrection=1.00¦YCorrection=1.00¦PrintKind=0¦BorderSize=5000000¦LeftOffset=0¦BottomOffset=0¦Orientation=2¦PaperLength=1000¦PaperWidth=1000¦Scale=100¦PaperSource=15¦PrintQuality=600¦MediaType=1¦DitherType=10¦PaperKind=Letter¦PrintScaleMode=1
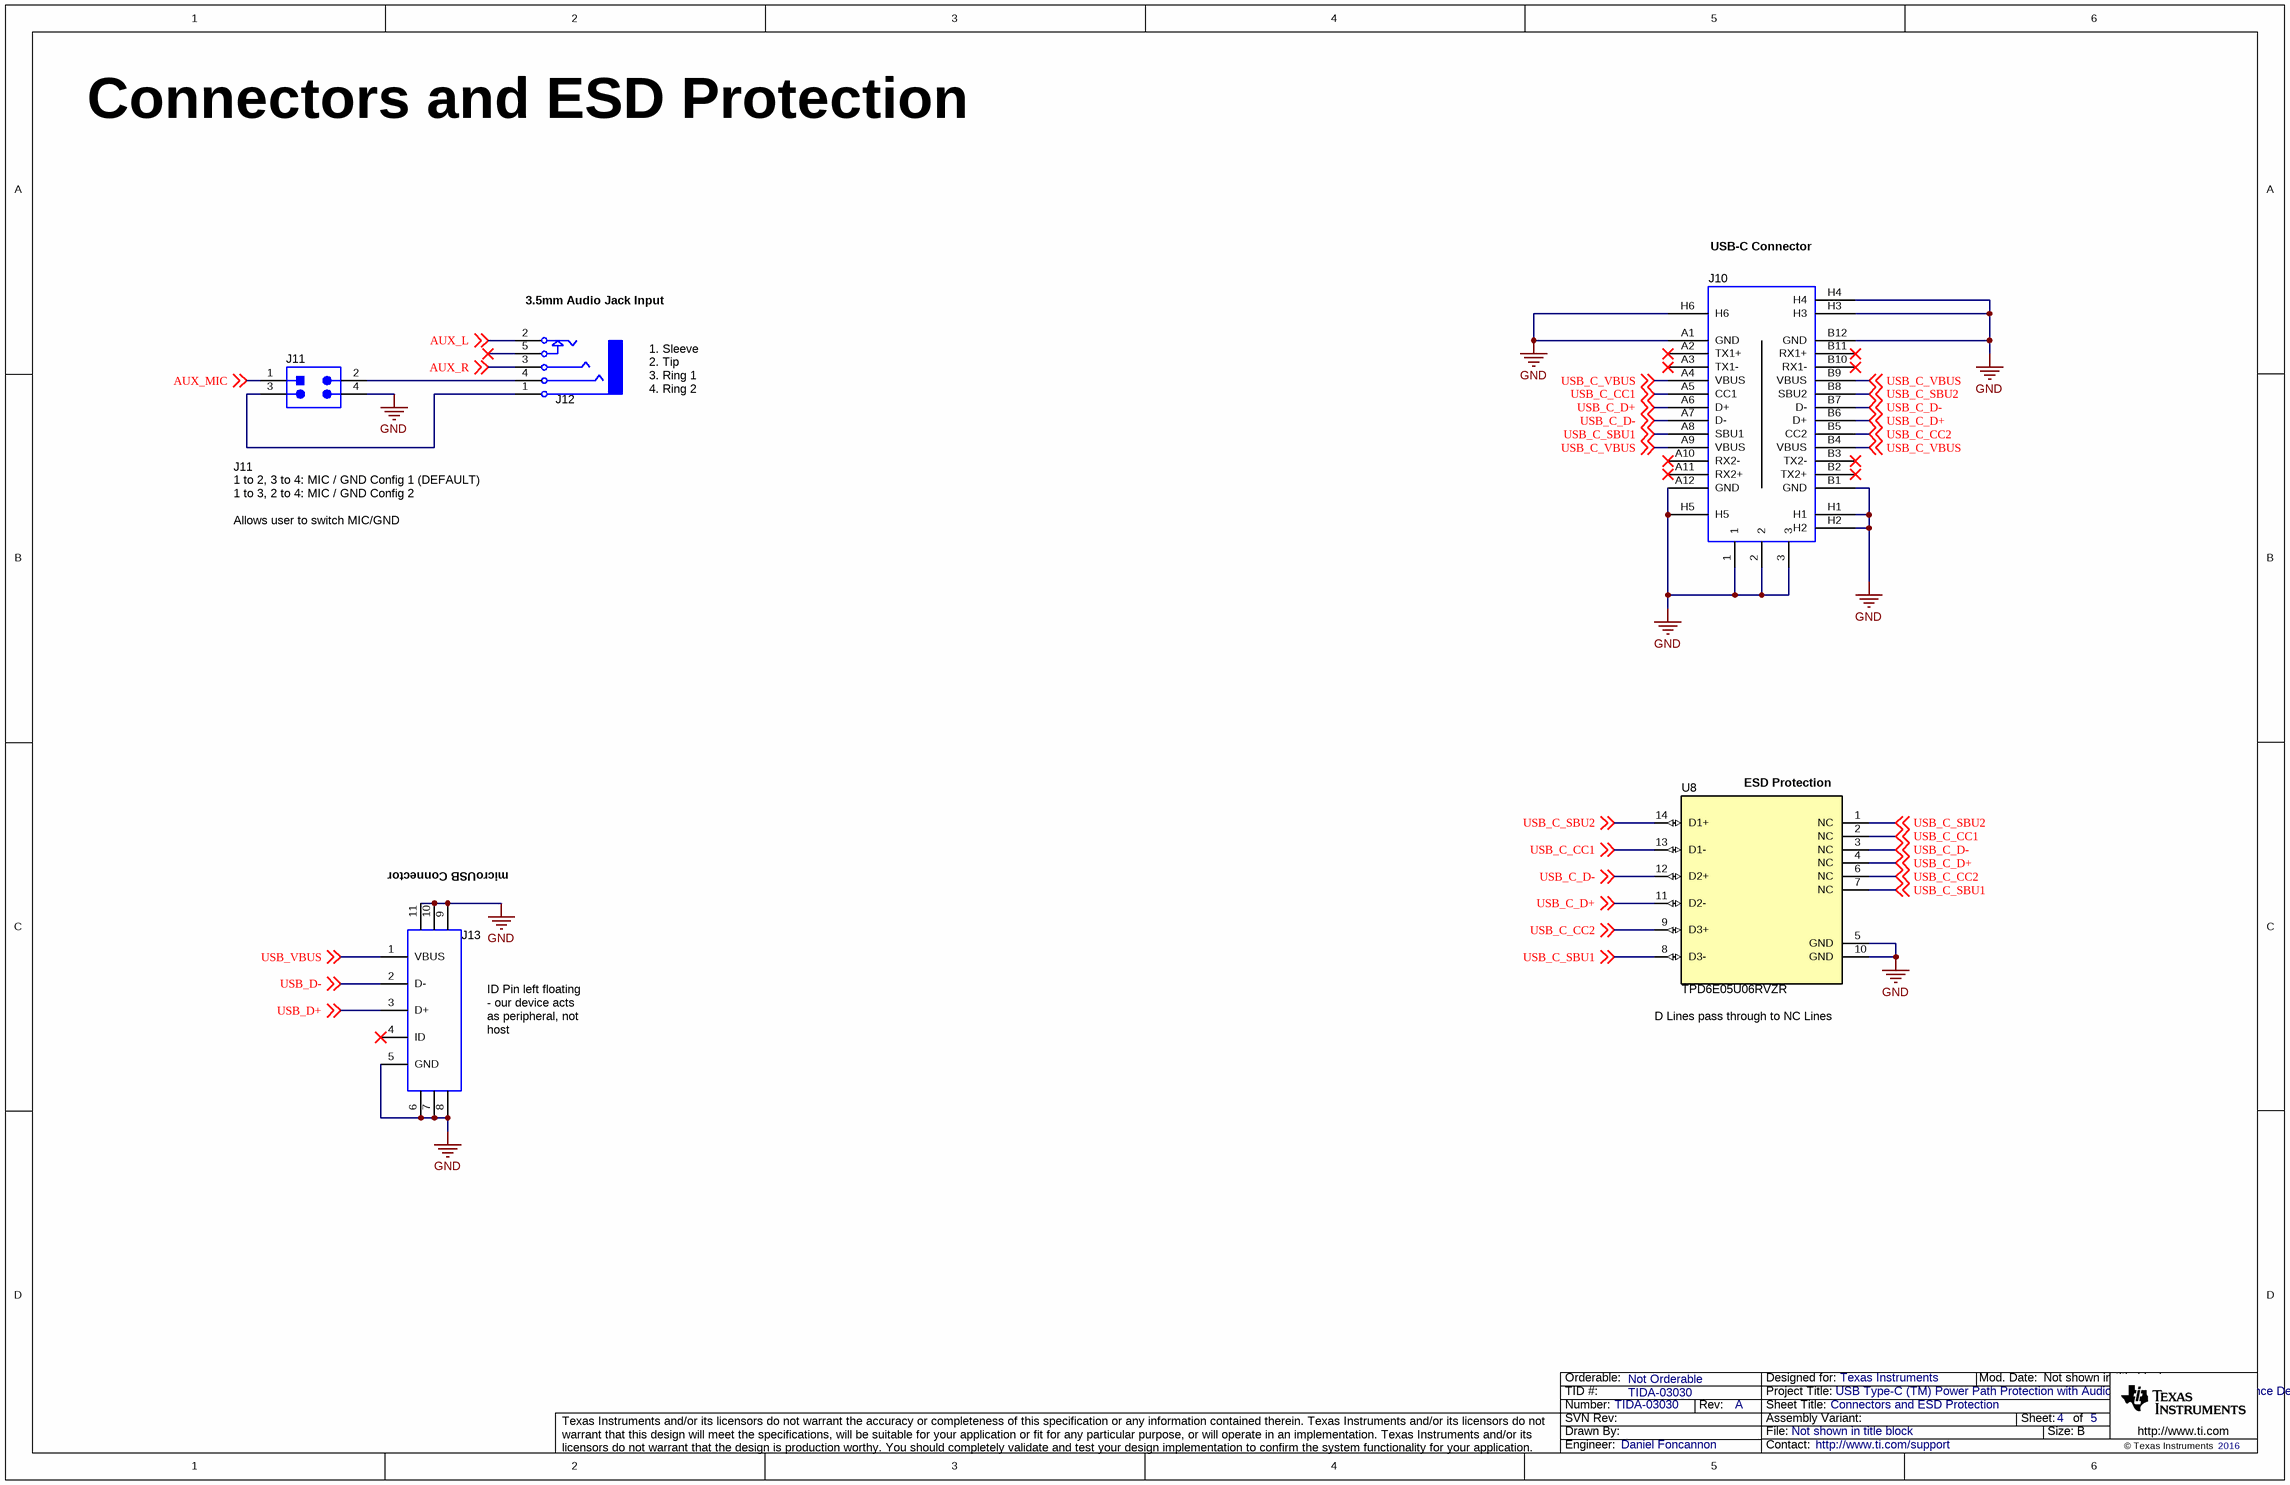
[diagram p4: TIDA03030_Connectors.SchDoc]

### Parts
J10  20-0000016-01  [Lintes_20-0000016-01]  (value not drawn)
J11  15-91-2040  [Molex_15-91-2040]  (value not drawn)
J12  SJ-43515TS-SMT-TR  [CUI_SJ-43515TS-SMT]  (value not drawn)
J13  0473460001  [CONN_47346-0001]  (value not drawn)
U8  TPD6E05U06RVZR  [RVZ0014A]

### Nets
GND: J10.1 J10.2 J10.3 J10.A1(GND) J10.A12(GND) J10.B1(GND) J10.B12(GND) J10.H1 J10.H2 J10.H3 J10.H4 J10.H5 J10.H6 J11.4 J13.5(GND) J13.6 J13.7 J13.8 J13.9 J13.10 J13.11 U8.5(GND) U8.10(GND)
AUX_L: J12.2(TIP) ; off-sheet AUX_L
AUX_MIC: J11.1 ; off-sheet AUX_MIC
AUX_R: J12.3(RING_1) ; off-sheet AUX_R
USB_C_CC1: J10.A5(CC1) U8.2(NC) U8.13(D1-) ; off-sheet USB_C_CC1
USB_C_CC2: J10.B5(CC2) U8.6(NC) U8.9(D3+) ; off-sheet USB_C_CC2
USB_C_D+: J10.A6(D+) J10.B6(D+) U8.4(NC) U8.11(D2-) ; off-sheet USB_C_D+
USB_C_D-: J10.A7(D-) J10.B7(D-) U8.3(NC) U8.12(D2+) ; off-sheet USB_C_D-
USB_C_SBU1: J10.A8(SBU1) U8.7(NC) U8.8(D3-) ; off-sheet USB_C_SBU1
USB_C_SBU2: J10.B8(SBU2) U8.1(NC) U8.14(D1+) ; off-sheet USB_C_SBU2
USB_C_VBUS: J10.A4(VBUS) J10.A9(VBUS) J10.B4(VBUS) J10.B9(VBUS) ; off-sheet USB_C_VBUS
USB_D+: J13.3(D+) ; off-sheet USB_D+
USB_D-: J13.2(D-) ; off-sheet USB_D-
USB_VBUS: J13.1(VBUS) ; off-sheet USB_VBUS
NetJ11_2: J11.2 J12.4(RING_2)
NetJ11_3: J11.3 J12.1(SLEEVE)

Not connected (* = marked no-connect by the designer): J10 A2(TX1+)* A3(TX1-)* A10(RX2-)* A11(RX2+)* B2(TX2+)* B3(TX2-)* B10(RX1-)* B11(RX1+)*; J12 5(TIP_SWITCH)*; J13 4(ID)*

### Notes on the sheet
- Connectors and ESD Protection
- (near J12) 3.5mm Audio Jack Input
- (near J10) USB-C Connector
- 1. Sleeve
  2. Tip
  3. Ring 1
  4. Ring 2
- J11
  1 to 2, 3 to 4: MIC / GND Config 1 (DEFAULT)
  1 to 3, 2 to 4: MIC / GND Config 2
  Allows user to switch MIC/GND
- (near U8) ESD Protection
- (near J13) microUSB Connector
- (near U8) D Lines pass through to NC Lines
- (near J13) ID Pin left floating - our device acts as peripheral, not host

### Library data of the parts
J10 = 20-0000016-01: Connector, Receptacle, USB Type C, R/A, SMT; Manufacturer: Lintes Technology; SymbolCreator: Altium
J11 = 15-91-2040: Header, 100mil, 2x2, Tin, SMT; Manufacturer: Molex; SymbolCreator: a0412235
J12 = SJ-43515TS-SMT-TR: Audio Jack, 3.5mm, Stereo, R/A, SMT; Manufacturer: CUI Inc.; SymbolCreator: Altium
J13 = 0473460001: Connector, Receptacle, Micro-USB Type B, R/A, Bottom Mount SMT; Manufacturer: Molex; SymbolCreator: a0411947
U8 = TPD6E05U06RVZR: 1, 4, 6 Channel ESD Protection Device for Super-Speed (up to 6 Gbps) Interface, RVZ0014A; Manufacturer: Texas Instruments; SymbolCreator: Altium; SizeArea_mm2: 4.725; SizeAreaWB_mm2: 10.575; SizeX_mm: 1.35; SizeY_mm: 3.5; SizeZ_mm: 0.55; CompType: IC; U/M: EA

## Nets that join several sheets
3V3: TIDA03030_Power (C8.1 TP15.1 U7.1), TIDA03030_Controller&Switches (C3.1 J1.3 U5.A1)
5V0: TIDA03030_Power (10 pins), TIDA03030_Controller&Switches (J1.1 R7.2 R10.2)
GND: TIDA03030_Power (20 pins), TIDA03030_Controller&Switches (12 pins), TIDA03030_Connectors (23 pins)
AUX_L: TIDA03030_Controller&Switches (U4.3 U5.C2), TIDA03030_Connectors (J12.2)
AUX_MIC: TIDA03030_Controller&Switches (U5.B1), TIDA03030_Connectors (J11.1)
AUX_R: TIDA03030_Controller&Switches (U4.2), TIDA03030_Connectors (J12.3)
PWR_EN: TIDA03030_Power (U6.2), TIDA03030_Controller&Switches (TP2.1 U1.B2)
USB_C_CC1: TIDA03030_Controller&Switches (U2.1), TIDA03030_Connectors (J10.A5 U8.2 U8.13)
USB_C_CC2: TIDA03030_Controller&Switches (U2.2), TIDA03030_Connectors (J10.B5 U8.6 U8.9)
USB_C_D+: TIDA03030_Controller&Switches (U4.7), TIDA03030_Connectors (J10.A6 J10.B6 U8.4 U8.11)
USB_C_D-: TIDA03030_Controller&Switches (U4.6), TIDA03030_Connectors (J10.A7 J10.B7 U8.3 U8.12)
USB_C_SBU1: TIDA03030_Controller&Switches (U5.A3), TIDA03030_Connectors (J10.A8 U8.7 U8.8)
USB_C_SBU2: TIDA03030_Controller&Switches (U5.B3), TIDA03030_Connectors (J10.B8 U8.1 U8.14)
USB_C_VBUS: TIDA03030_Power (9 pins), TIDA03030_Controller&Switches (R3.2), TIDA03030_Connectors (J10.A4 J10.A9 J10.B4 J10.B9)
USB_D+: TIDA03030_Controller&Switches (U4.10), TIDA03030_Connectors (J13.3)
USB_D-: TIDA03030_Controller&Switches (U4.1), TIDA03030_Connectors (J13.2)
USB_VBUS: TIDA03030_Power (J8.3), TIDA03030_Connectors (J13.1)

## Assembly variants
001: not fitted C7 C8 FID1 FID2 FID3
